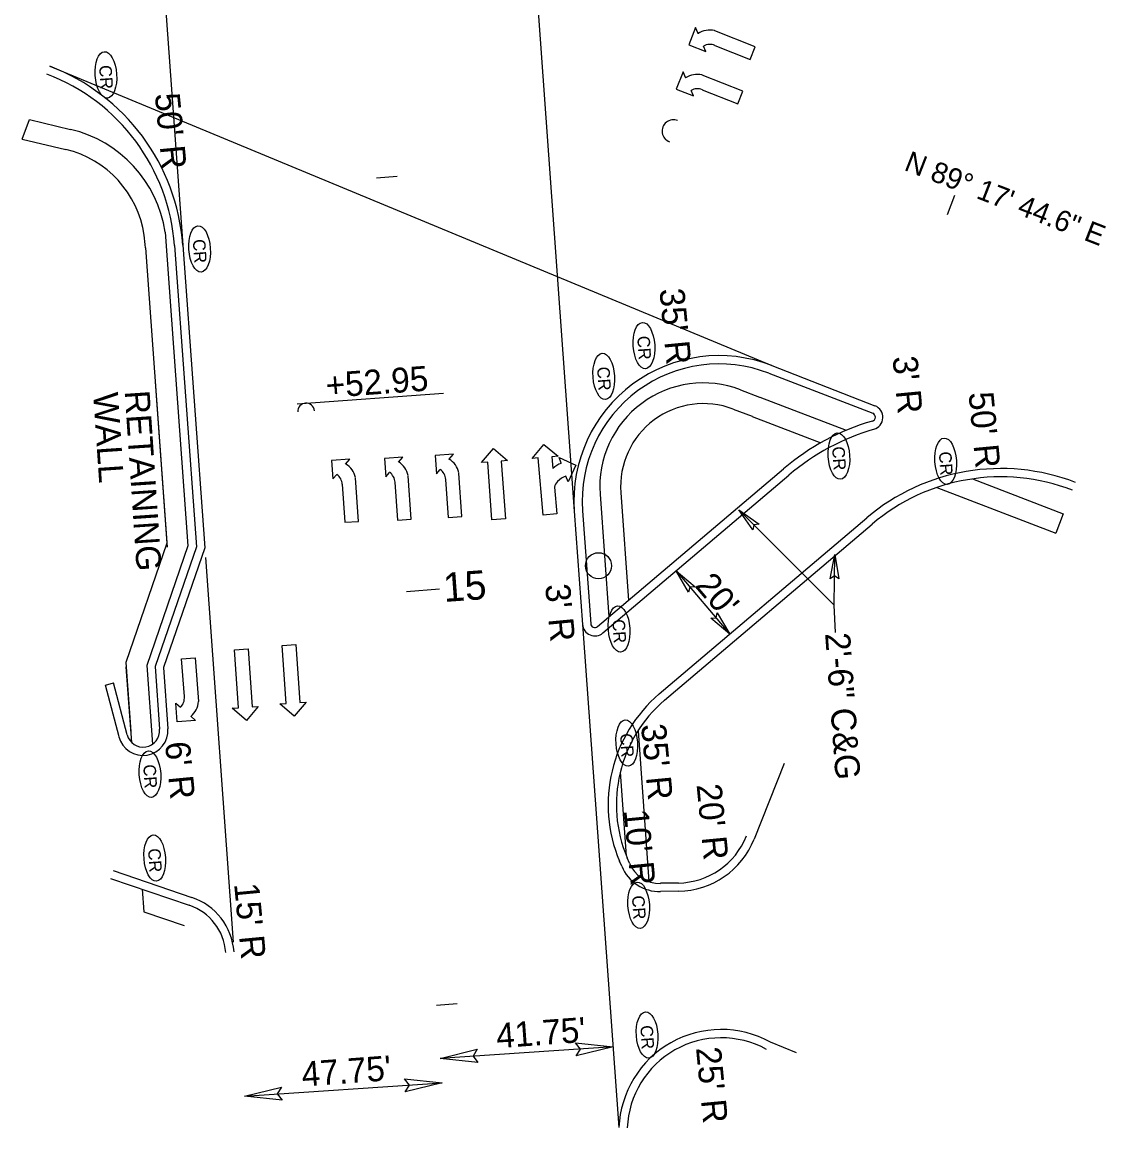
# Model space of a CAD drawing. Extents: x 2131049 to 2132623, y 643184 to 644993.
# Drawn here: x 2132361.9 to 2132623.2, y 643446.4 to 643713 of the extents above; entities that cross this region are included whole.
import ezdxf

# ---------------------------------------------------------------- set-up
doc = ezdxf.new("R2010")
doc.units = 0
for name, color, linetype in [('Prop Conc 2ft 6in Curb and Gutter', 7, 'Continuous'), ('Prop Conc 4in Sidewalk', 7, 'Continuous'), ('Prop Conc 5in Monolithic Keyed In Island', 7, 'Continuous'), ('Prop Dimension Text', 7, 'Continuous'), ('Prop DSN Text', 7, 'Continuous'), ('Prop EOT', 7, 'Continuous'), ('Prop Horizontal Alignment Direction Label', 7, 'Continuous'), ('Prop Horizontal Alignment Station Label', 7, 'Continuous'), ('Prop Horizontal Alignment Tick Label', 7, 'Continuous'), ('Prop Horizontal Alignment Tick Large', 7, 'Continuous'), ('Prop Horizontal Alignment Tick Small', 7, 'Continuous'), ('Prop Lane Arrow CELL', 7, 'Continuous'), ('Prop Lane Lines', 7, 'Continuous'), ('Prop Retaining Wall', 7, 'Continuous'), ('Prop Terminator CELL', 7, 'Continuous'), ('Prop WCC CELL', 7, 'Continuous'), ('Scratch_Level_3', 7, 'Continuous')]:
    doc.layers.add(name, color=color, linetype=linetype)

msp = doc.modelspace()

# ---------------------------------------------------------------- linework, layer by layer
at = {"layer": 'Prop Conc 2ft 6in Curb and Gutter'}
for p, q in [((2132398.63, 643659.14), (2132403.89, 643586.52)), ((2132541.91, 643628.36), (2132566.94, 643618.73)), ((2132500.62, 643567.27), (2132545.43, 643605.33)), ((2132497, 643595.23), (2132498.98, 643567.96)), ((2132516.79, 643549.51), (2132566.79, 643591.97)), ((2132403.89, 643586.52), (2132393.94, 643557.68)), ((2132393.94, 643557.68), (2132395.04, 643542.51)), ((2132382, 643553.19), (2132383.93, 643553.69)), ((2132387.18, 643541.21), (2132383.93, 643553.69)), ((2132508.28, 643510.26), (2132507.75, 643511.52)), ((2132383.16, 643506.54), (2132402.19, 643500.08)), ((2132520.09, 643505.45), (2132515.79, 643505.38)), ((2132410.97, 643488.71), (2132410.97, 643488.71))]:
    msp.add_line(p, q, dxfattribs=at)
for centre, radius, start, end in [((2132350.75, 643655.68), 48, 4.1431, 69.1069), ((2132529.91, 643597.62), 33, 68.692, 184.1431), ((2132566.58, 643617.79), 1, 286.138, 68.9456), ((2132582.98, 643561.12), 58, 106.138, 130.3412), ((2132597.86, 643555.39), 48, 68.9456, 130.3412), ((2132499.97, 643568.03), 1, 184.1431, 310.3412), ((2132538.15, 643524.36), 33, 130.3412, 202.8952), ((2132391.05, 643542.22), 4, 194.6073, 4.1431), ((2132519.79, 643523.45), 18, 270.9773, 338.2949), ((2132515.65, 643513.37), 8, 202.8952, 270.9773), ((2132398.01, 643487.77), 13, 4.1431, 71.2483), ((2132530.41, 643445.47), 22.66, 61.2154, 177.6505)]:
    msp.add_arc(centre, radius, start, end, dxfattribs=at)
at = {"layer": 'Prop Conc 4in Sidewalk'}
for p, q in [((2132361.89, 643684.86), (2132363.69, 643689.57)), ((2132363.69, 643689.57), (2132373.58, 643687.19)), ((2132361.89, 643684.86), (2132372.42, 643682.33)), ((2132396.38, 643662.43), (2132401.86, 643586.78)), ((2132391.64, 643658.64), (2132396.88, 643586.42)), ((2132393.99, 643626.3), (2132396.8, 643587.44)), ((2132535.09, 643624.4), (2132539.68, 643622.64)), ((2132539.7, 643622.63), (2132560.55, 643614.61)), ((2132533.3, 643619.73), (2132537.86, 643617.99)), ((2132537.91, 643617.97), (2132554.43, 643611.61)), ((2132590.98, 643602.89), (2132612.9, 643594.46)), ((2132582.41, 643600.84), (2132611.1, 643589.79)), ((2132501.22, 643599.24), (2132503.37, 643569.6)), ((2132506.21, 643599.6), (2132508.09, 643573.61)), ((2132612.9, 643594.46), (2132611.1, 643589.79)), ((2132401.86, 643586.78), (2132391.92, 643557.94)), ((2132386.93, 643557.58), (2132388.25, 643539.37)), ((2132391.92, 643557.94), (2132393.3, 643538.91)), ((2132510.37, 643542.17), (2132513, 643505.83)), ((2132506.08, 643532.14), (2132507.54, 643512.04)), ((2132390.82, 643503.94), (2132391.21, 643498.53)), ((2132391.21, 643498.53), (2132400.98, 643495.21))]:
    msp.add_line(p, q, dxfattribs=at)
for centre, radius, start, end in [((2132366.65, 643657.93), 30.07, 8.6086, 76.6667), ((2132366.58, 643658.02), 25, 8.4362, 76.4943), ((2132350.75, 643655.68), 41, 4.1431, 8.4362), ((2132526.16, 643601.05), 25, 69.0738, 184.1431), ((2132526.16, 643601.05), 20, 69.0738, 184.1431)]:
    msp.add_arc(centre, radius, start, end, dxfattribs=at)
at = {"layer": 'Prop Conc 5in Monolithic Keyed In Island'}
for centre, radius, start, end in [((2132518.93, 643686.76), 2.75, 68.7631, 248.7903), ((2132430.35, 643619.18), 2, 93.102, 184.0452), ((2132430.35, 643619.19), 2, 4.1101, 92.9712)]:
    msp.add_arc(centre, radius, start, end, dxfattribs=at)
at = {"layer": 'Prop DSN Text'}
for p, q in [((2132428.21, 643621.03), (2132463.46, 643623.59)), ((2132557.67, 643572.45), (2132534.64, 643595.44)), ((2132557.67, 643572.45), (2132557.78, 643584.66)), ((2132519.55, 643580.72), (2132532.5, 643565.48)), ((2132557.97, 643565.89), (2132557.67, 643572.45)), ((2132504.36, 643465.96), (2132462.7, 643463.14)), ((2132415.49, 643454.06), (2132463.13, 643457.27))]:
    msp.add_line(p, q, dxfattribs=at)
at = {"layer": 'Prop EOT'}
for p, q in [((2132400.62, 643659.29), (2132405.91, 643586.25)), ((2132542.63, 643630.22), (2132567.48, 643620.53)), ((2132501.92, 643565.74), (2132546.73, 643603.8)), ((2132495.01, 643595.09), (2132496.98, 643567.81)), ((2132515.5, 643551.04), (2132565.49, 643593.5)), ((2132405.91, 643586.25), (2132395.97, 643557.41)), ((2132395.97, 643557.41), (2132397.04, 643542.66)), ((2132385.25, 643540.71), (2132382, 643553.19)), ((2132545.61, 643534.24), (2132538.37, 643516.05)), ((2132506.44, 643509.48), (2132505.91, 643510.74)), ((2132383.81, 643508.43), (2132402.83, 643501.97)), ((2132520.13, 643503.45), (2132515.82, 643503.38)), ((2132548.59, 643464.5), (2132542.28, 643467.08))]:
    msp.add_line(p, q, dxfattribs=at)
for centre, radius, start, end in [((2132350.75, 643655.68), 50, 4.1431, 69.1069), ((2132529.91, 643597.62), 35, 68.692, 184.1431), ((2132566.39, 643617.74), 3, 286.3272, 68.692), ((2132582.98, 643561.12), 56, 106.138, 130.3412), ((2132597.86, 643555.39), 50, 68.9456, 130.3412), ((2132499.97, 643568.03), 3, 184.1431, 310.3412), ((2132538.15, 643524.36), 35, 130.3412, 202.8952), ((2132391.05, 643542.22), 6, 194.6073, 4.1431), ((2132519.79, 643523.45), 20, 270.9773, 338.2949), ((2132515.65, 643513.37), 10, 202.8952, 270.9773), ((2132398.01, 643487.77), 15, 4.1431, 71.2483), ((2132530.41, 643445.47), 24.66, 61.2154, 177.6505)]:
    msp.add_arc(centre, radius, start, end, dxfattribs=at)
at = {"layer": 'Prop Horizontal Alignment Station Label'}
msp.add_line((2132586.7, 643671.22), (2132584.89, 643666.56), dxfattribs=at)
at = {"layer": 'Prop Horizontal Alignment Tick Large'}
msp.add_line((2132454.55, 643575.77), (2132462.53, 643576.35), dxfattribs=at)
at = {"layer": 'Prop Horizontal Alignment Tick Small'}
for p, q in [((2132447.32, 643675.51), (2132452.31, 643675.87)), ((2132461.77, 643476.03), (2132466.76, 643476.39))]:
    msp.add_line(p, q, dxfattribs=at)
at = {"layer": 'Prop Lane Arrow CELL'}
for p, q in [((2132524.24, 643711.72), (2132522.61, 643707.6)), ((2132528.88, 643710.94), (2132528.82, 643710.99)), ((2132538.64, 643707.07), (2132528.88, 643710.94)), ((2132522.61, 643707.6), (2132526.73, 643705.97)), ((2132526.18, 643707.24), (2132526.17, 643707.27)), ((2132526.73, 643705.97), (2132526.18, 643707.24)), ((2132537.43, 643704.02), (2132538.64, 643707.07)), ((2132521.22, 643701.03), (2132519.59, 643696.91)), ((2132521.87, 643699.54), (2132521.22, 643701.03)), ((2132535.62, 643696.39), (2132525.86, 643700.25)), ((2132519.59, 643696.91), (2132523.71, 643695.28)), ((2132523.71, 643695.28), (2132523.16, 643696.56)), ((2132525.87, 643696.72), (2132534.41, 643693.34)), ((2132534.41, 643693.34), (2132535.62, 643696.39)), ((2132453.65, 643608.14), (2132449.23, 643607.83)), ((2132452.59, 643606.91), (2132453.65, 643608.14)), ((2132465.86, 643608.84), (2132461.45, 643608.53)), ((2132461.45, 643608.53), (2132461.76, 643604.11)), ((2132464.8, 643607.61), (2132465.86, 643608.84)), ((2132472.67, 643606.86), (2132475.55, 643610.2)), ((2132475.55, 643610.2), (2132478.89, 643607.32)), ((2132440.93, 643607.65), (2132436.51, 643607.33)), ((2132436.51, 643607.33), (2132436.82, 643602.92)), ((2132439.87, 643606.42), (2132440.93, 643607.65)), ((2132449.23, 643607.83), (2132449.54, 643603.41)), ((2132474.14, 643606.97), (2132472.67, 643606.86)), ((2132475.16, 643593.06), (2132474.14, 643606.97)), ((2132478.89, 643607.32), (2132477.41, 643607.21)), ((2132477.41, 643607.21), (2132478.43, 643593.3)), ((2132436.82, 643602.92), (2132437.74, 643603.97)), ((2132442.97, 643592.66), (2132442.24, 643603.13)), ((2132449.54, 643603.41), (2132450.45, 643604.46)), ((2132455.69, 643593.15), (2132454.95, 643603.62)), ((2132461.76, 643604.11), (2132462.67, 643605.16)), ((2132463.99, 643602.79), (2132464.63, 643593.62)), ((2132467.9, 643593.85), (2132467.17, 643604.32)), ((2132439.05, 643601.59), (2132439.7, 643592.43)), ((2132451.77, 643602.08), (2132452.42, 643592.92)), ((2132439.7, 643592.43), (2132442.97, 643592.66)), ((2132452.42, 643592.92), (2132455.69, 643593.15)), ((2132464.63, 643593.62), (2132467.9, 643593.85)), ((2132478.43, 643593.3), (2132475.16, 643593.06))]:
    msp.add_line(p, q, dxfattribs=at)
for points in [[(2132524.85, 643710.31), (2132524.89, 643710.23), (2132524.85, 643710.31), (2132524.24, 643711.72)], [(2132528.9, 643707.43), (2132528.89, 643707.41), (2132537.43, 643704.02)]]:
    msp.add_lwpolyline(points, dxfattribs=at)
for centre, radius, start, end in [((2132527.65, 643705.9), 5.22, 77.0671, 122.3788), ((2132527.7, 643704.4), 3.26, 68.391, 118.0492), ((2132524.63, 643695.21), 5.22, 77.0671, 122.3788), ((2132524.68, 643693.71), 3.26, 68.391, 118.0492), ((2132437.16, 643602.06), 5.22, 12.6936, 58.0053), ((2132449.88, 643602.55), 5.22, 12.6936, 58.0053), ((2132460.76, 643602.56), 3.26, 4.0175, 53.6757), ((2132462.09, 643603.25), 5.22, 12.6936, 58.0053), ((2132435.83, 643601.37), 3.26, 4.0175, 53.6757), ((2132448.55, 643601.86), 3.26, 4.0175, 53.6757)]:
    msp.add_arc(centre, radius, start, end, dxfattribs=at)
at = {"layer": 'Prop Lane Lines'}
for p, q in [((2132390.17, 643803.61), (2132400.62, 643659.29)), ((2132481.73, 643778.16), (2132495.01, 643595.09)), ((2132368.58, 643702.39), (2132542.63, 643630.22)), ((2132406.08, 643583.95), (2132412.8, 643491.18)), ((2132496.98, 643567.81), (2132505.77, 643446.48))]:
    msp.add_line(p, q, dxfattribs=at)
at = {"layer": 'Prop Retaining Wall'}
for p, q in [((2132393.99, 643626.3), (2132396.8, 643587.44)), ((2132396.8, 643587.44), (2132386.86, 643558.6)), ((2132386.86, 643558.6), (2132388.06, 643542))]:
    msp.add_line(p, q, dxfattribs=at)
at = {"layer": 'Prop Terminator CELL'}
for p, q in [((2132484.83, 643607.82), (2132487.7, 643611.17)), ((2132487.7, 643611.17), (2132491.1, 643608.35)), ((2132486.32, 643607.94), (2132484.83, 643607.82)), ((2132487.5, 643594.19), (2132486.32, 643607.94)), ((2132491.1, 643608.35), (2132489.61, 643608.23)), ((2132489.61, 643608.23), (2132489.85, 643605.39)), ((2132491.33, 643608.07), (2132495.35, 643606.21)), ((2132491.85, 643606.66), (2132491.33, 643608.07)), ((2132495.35, 643606.21), (2132493.49, 643602.18)), ((2132493.49, 643602.18), (2132492.97, 643603.55)), ((2132490.24, 643600.9), (2132490.79, 643594.48)), ((2132490.79, 643594.48), (2132487.5, 643594.19)), ((2132424.58, 643562.7), (2132427.87, 643562.93)), ((2132425.55, 643548.74), (2132424.58, 643562.7)), ((2132427.87, 643562.93), (2132428.84, 643548.97)), ((2132413.06, 643561.66), (2132416.35, 643561.89)), ((2132414.03, 643547.69), (2132413.06, 643561.66)), ((2132416.35, 643561.89), (2132417.33, 643547.92)), ((2132400.34, 643559.52), (2132403.63, 643559.76)), ((2132401, 643550.4), (2132400.34, 643559.52)), ((2132403.63, 643559.76), (2132404.4, 643549.24)), ((2132399.29, 643544.31), (2132398.92, 643548.79)), ((2132398.92, 643548.79), (2132400.04, 643547.82)), ((2132412.54, 643547.59), (2132414.03, 643547.69)), ((2132415.95, 643544.67), (2132412.54, 643547.59)), ((2132418.82, 643548.03), (2132415.95, 643544.67)), ((2132417.33, 643547.92), (2132418.82, 643548.03)), ((2132424.05, 643548.63), (2132425.55, 643548.74)), ((2132427.46, 643545.71), (2132424.05, 643548.63)), ((2132430.34, 643549.07), (2132427.46, 643545.71)), ((2132428.84, 643548.97), (2132430.34, 643549.07)), ((2132403.68, 643544.67), (2132399.29, 643544.31)), ((2132402.55, 643545.65), (2132403.68, 643544.67))]:
    msp.add_line(p, q, dxfattribs=at)
for points in [[(2132538.07, 643590.59), (2132534.64, 643595.44), (2132539.54, 643592.02), (2132538.27, 643591.81)], [(2132556.72, 643578.82), (2132557.78, 643584.66), (2132558.77, 643578.77), (2132557.73, 643579.53)], [(2132522.57, 643575.61), (2132519.55, 643580.72), (2132524.15, 643576.91), (2132522.87, 643576.81)], [(2132529.48, 643570.59), (2132532.5, 643565.48), (2132527.9, 643569.29), (2132529.17, 643569.39)], [(2132495.28, 643466.9), (2132504.36, 643465.96), (2132495.44, 643463.75), (2132496.48, 643465.42)], [(2132471.79, 643462.2), (2132462.7, 643463.14), (2132471.63, 643465.35), (2132470.59, 643463.68)], [(2132424.57, 643453.12), (2132415.49, 643454.06), (2132424.41, 643456.26), (2132423.37, 643454.59)], [(2132454.05, 643458.21), (2132463.13, 643457.27), (2132454.21, 643455.07), (2132455.25, 643456.74)]]:
    msp.add_lwpolyline(points, close=True, dxfattribs=at)
for centre, radius, start, end in [((2132493.11, 643602.4), 4.43, 106.4833, 137.3619), ((2132494.24, 643599.29), 4.43, 106.6021, 137.4557), ((2132492.72, 643600.47), 2.52, 133.9656, 170.2776), ((2132397.76, 643550.15), 3.27, 314.485, 4.1431), ((2132399.18, 643549.65), 5.25, 310.1554, 355.4671)]:
    msp.add_arc(centre, radius, start, end, dxfattribs=at)
at = {"layer": 'Prop WCC CELL'}
for centre in [(2132382.08, 643700.33), (2132404.67, 643658.36), (2132511.8, 643635.05), (2132502.12, 643627.61), (2132558.79, 643608.39), (2132584.53, 643607.16), (2132505.8, 643566.7), (2132507.66, 643539.2), (2132392.71, 643531.7), (2132393.86, 643511.46), (2132510.52, 643500.09), (2132512.55, 643468.8)]:
    msp.add_ellipse(centre, major_axis=(0.38, -5.59), ratio=0.462467, dxfattribs=at)
at = {"layer": 'Scratch_Level_3'}
msp.add_circle((2132500.84, 643581.96), 3.15, dxfattribs=at)

# ---------------------------------------------------------------- texts
at = {"layer": 'Prop Dimension Text'}
msp.add_text("47.75'", height=6, rotation=4.1585, dxfattribs=at).set_placement((2132429.49, 643456.35))
at = {"layer": 'Prop DSN Text'}
for s, rotation, p in [("50' R", 275.472, (2132393.87, 643695.7)), ("35' R", 275.472, (2132515.52, 643648.6)), ("3' R", 275.472, (2132571.71, 643632.3)), ('+52.95', 4.1431, (2132435.3, 643622.43)), ('WALL', 273.8612, (2132379.01, 643623.55)), ('RETAINING', 273.8612, (2132386.6, 643624.06)), ("50' R", 275.472, (2132590.04, 643623.63)), ("20'", 310.3412, (2132523.87, 643577.07)), ("3' R", 275.472, (2132487.96, 643577.34)), ('2\'-6" C&G', 274.1585, (2132555.46, 643565.64)), ("35' R", 275.472, (2132511.08, 643543.58)), ("6' R", 275.472, (2132396.33, 643539.32)), ("20' R", 275.472, (2132524.48, 643529.13)), ("10' R", 275.472, (2132506.9, 643523)), ("15' R", 275.472, (2132412.99, 643505.22)), ("41.75'", 4.1431, (2132476.38, 643465.6)), ("25' R", 275.472, (2132524.34, 643465.67))]:
    msp.add_text(s, height=6, rotation=rotation, dxfattribs=at).set_placement(p)
at = {"layer": 'Prop Horizontal Alignment Direction Label'}
msp.add_text('N 89%%d 17\' 44.6" E', height=5, rotation=338.7654, dxfattribs=at).set_placement((2132574.27, 643677.44))
at = {"layer": 'Prop Horizontal Alignment Tick Label'}
msp.add_text('15', height=7, rotation=4.1431, dxfattribs=at).set_placement((2132463.65, 643573.21))
at = {"layer": 'Prop WCC CELL'}
for p in [(2132380.45, 643702.58), (2132403.03, 643660.61), (2132510.17, 643637.3), (2132500.48, 643629.86), (2132557.15, 643610.64), (2132582.89, 643609.41), (2132504.17, 643568.95), (2132506.02, 643541.45), (2132391.08, 643533.96), (2132392.23, 643513.71), (2132508.89, 643502.35), (2132510.91, 643471.05)]:
    msp.add_text('CR', height=3, rotation=273.8612, dxfattribs=at).set_placement(p)

doc.saveas('drawing.dxf')
